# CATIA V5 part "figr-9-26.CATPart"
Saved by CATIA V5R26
Part number: Part1
Bounding box of the stored display mesh (mm): x -75 to 75, y -50 to 50, z 0 to 40
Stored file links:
  D:\_Deepak\CATIA\CATIA V5-6R2016_Deepak\Resources\Part files\Partfiles\c09_catia_v5_6r2016_prt\figr-9-26.CATPart
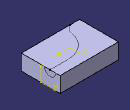
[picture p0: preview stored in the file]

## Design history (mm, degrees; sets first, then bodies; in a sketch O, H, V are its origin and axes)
Body1 (main body)
  Sketch1 on xy-plane, origin (0, 0, 0), H (1, 0, 0), V (0, 1, 0)
    line L1 (-75, 50) -> (75, 50)
    line L2 (75, 50) -> (75, -50)
    line L3 (75, -50) -> (-75, -50)
    line L4 (-75, -50) -> (-75, 50)
    axis line L5 (75, -50) -> (-75, 50)
    length L2 = 100
    length L3 = 150
    horizontal: L1 H, L3 H
    vertical: L2 V, L4 V
    midpoint: O L5
  Pad1: profile Sketch1, direction (0, 0, 1), length 40
  Sketch2 on face of Pad1, origin (75, 0, 0), H (0, 1, 0), V (0, 0, 1)
    arc A1 centre (24.1478, 40) radius 14.6047 from (9.543, 40) to (38.7525, 40) ccw
    point P1 (24.1478, 40)
    reference projected point E1 (24.1478, 40) from vertex of Sketch3
    line L1 (9.543, 40) -> (38.7525, 40)
    coincidence: P1 E1
    horizontal: L1 H
  Sketch3 on face of Pad1, origin (0, 0, 40), H (1, 0, 0), V (0, 1, 0)
    point P1 (75, 24.1478)
    line L1 (75, 24.1478) -> (28.6577, 24.1478)
    arc A1 centre (28.6577, -39.2062) radius 63.354 from (28.6577, 24.1478) to (-33.8383, -28.8149) ccw
    arc A2 centre (-62.192, -24.1005) radius 28.7429 from (-33.8383, -28.8149) to (-49.7271, -50) cw
    point P6 (-49.7271, -50)
    reference projected line E1 (75, -50) -> (75, 50) from edge [face of Pad1 | face of Pad1]
    reference projected line E2 (-75, -50) -> (75, -50) from edge [face of Pad1 | face of Pad1]
    horizontal: L1 H
    tangency: A1 L1, A2 A1
    coincidence: P1 E1, P6 E2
